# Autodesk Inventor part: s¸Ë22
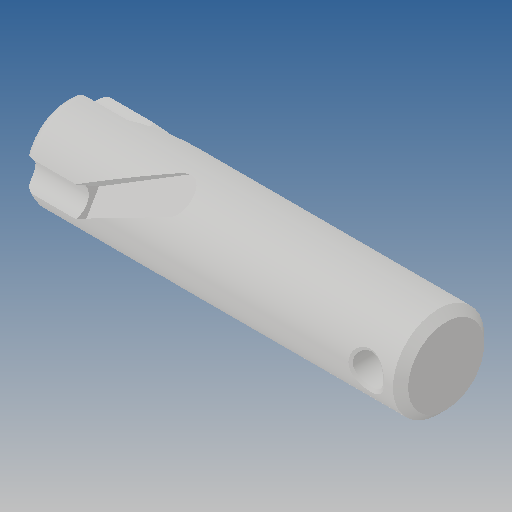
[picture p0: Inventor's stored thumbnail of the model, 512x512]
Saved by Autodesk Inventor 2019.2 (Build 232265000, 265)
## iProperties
Created: 2013-09
Part Number: s¸Ë22
Material: Ogólny
Document SubType Name: Modeling
Designer: CADENGINEERING4
Density: 1 g/cm^3
Appearance: Domyślna
Author: CADENGINEERING4
Revision Number: ÈÎºÎ
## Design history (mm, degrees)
feature "µ¹½Ç1"
node "Bryła1"
